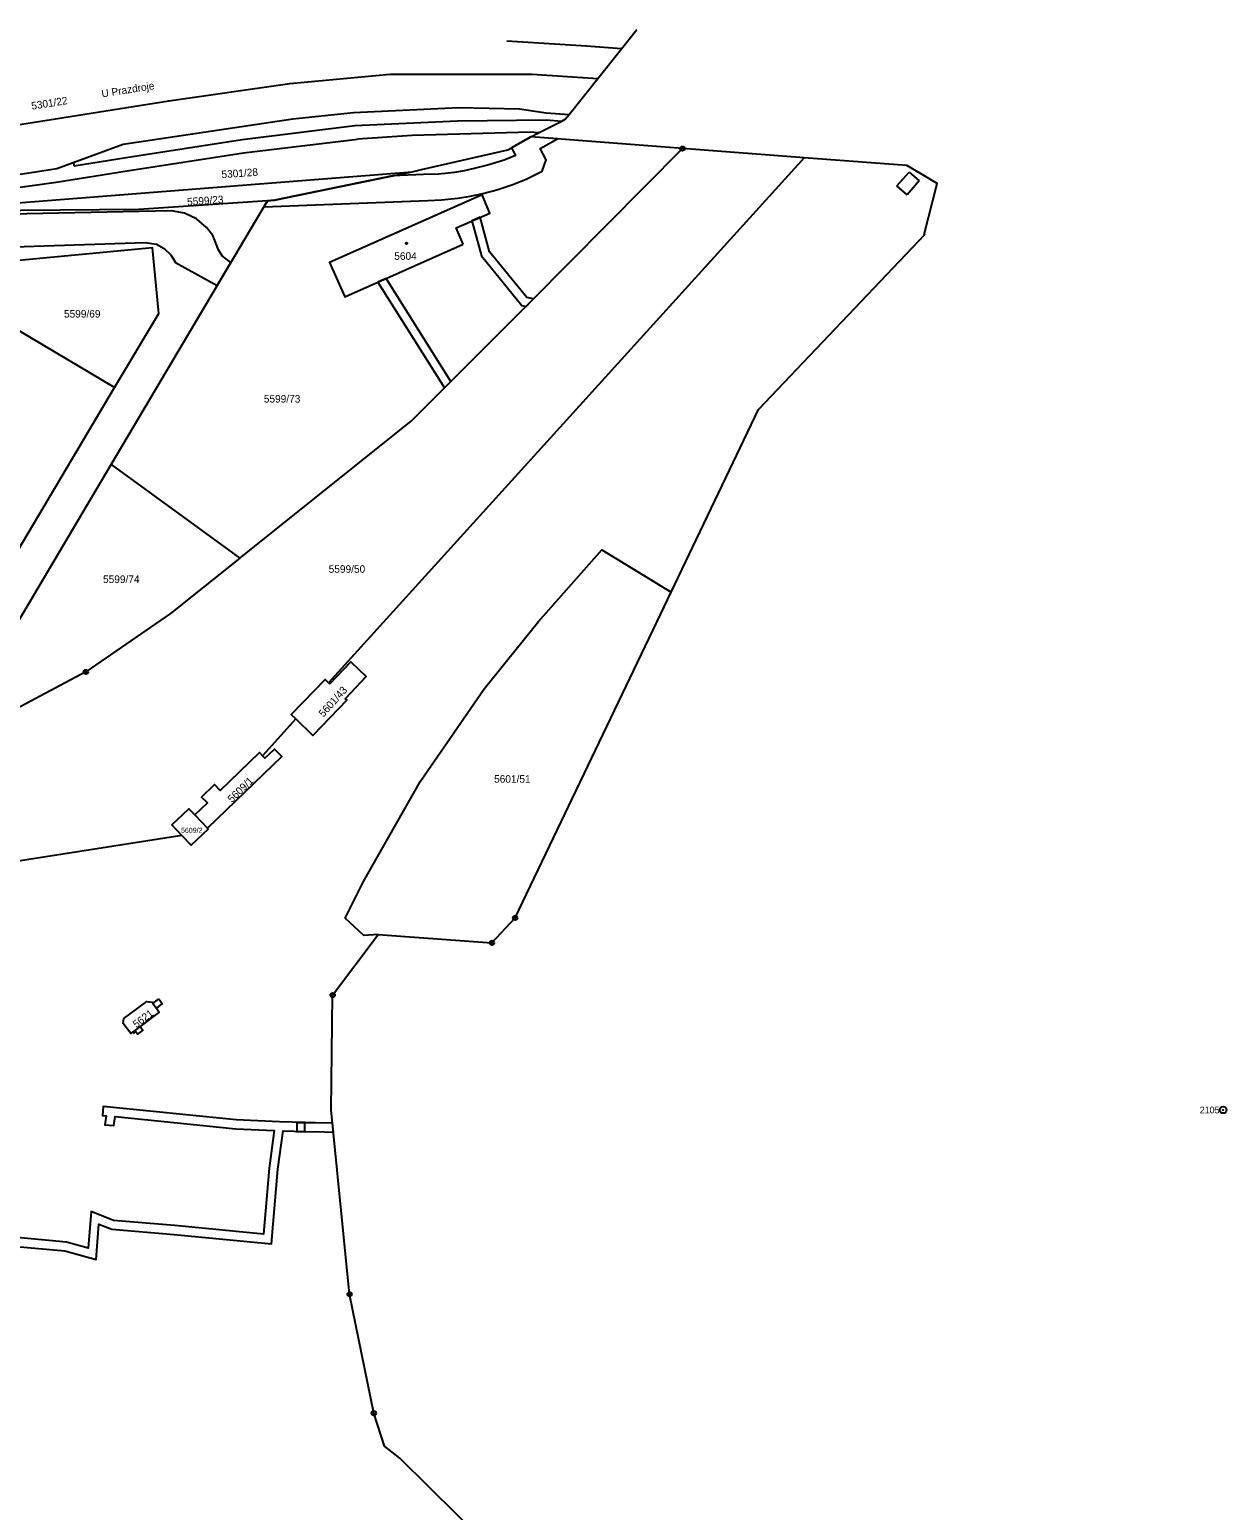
# Model space of a CAD drawing. Extents: x -821458 to -820266, y -1071458 to -1069826.
# Drawn here: x -820990.7 to -820721.4, y -1070158.9 to -1069825.7 of the extents above; entities that cross this region are included whole.
import ezdxf

# ---------------------------------------------------------------- set-up
doc = ezdxf.new("R2010")
doc.units = 0
for name, color, linetype in [('Vrstva 1', 7, 'Continuous'), ('Vrstva 13', 7, 'Continuous'), ('Vrstva 2', 7, 'Continuous'), ('Vrstva 4', 7, 'Continuous'), ('Vrstva 5', 7, 'Continuous'), ('Vrstva 7', 7, 'Continuous'), ('Vrstva 8', 7, 'Continuous')]:
    doc.layers.add(name, color=color, linetype=linetype)

msp = doc.modelspace()

# ---------------------------------------------------------------- linework, layer by layer
at = {"layer": 'Vrstva 1'}
for p, q in [((-820857.47, -1069830.03), (-820854.02, -1069825.73)), ((-820862.85, -1069836.75), (-820857.47, -1069830.03)), ((-820869.29, -1069844.79), (-820862.85, -1069836.75)), ((-820877.88, -1069849.87), (-820876.16, -1069848.95)), ((-820843.79, -1069852.49), (-820877.88, -1069849.87)), ((-820816.4, -1069854.6), (-820843.79, -1069852.49)), ((-820816.4, -1069854.6), (-820923.4, -1069972.68)), ((-820904.63, -1069857.69), (-820902.53, -1069857.21)), ((-820972.32, -1069923.54), (-820937.16, -1069864.21)), ((-820971.6, -1069906.22), (-821016.17, -1069879.84)), ((-821014.57, -1069978.75), (-820971.6, -1069906.22)), ((-821007, -1069982.04), (-820972.32, -1069923.54)), ((-820972.32, -1069923.54), (-820943.38, -1069944.62)), ((-820930.78, -1069980.82), (-820938.28, -1069989.09)), ((-820953.52, -1070002.4), (-820950.64, -1070005.41)), ((-820886.66, -1070031.18), (-820881.43, -1070025.58)), ((-820922.5, -1070042.94), (-820912.23, -1070029.33)), ((-820912.23, -1070029.33), (-820886.66, -1070031.18)), ((-820887.52, -1070166.75), (-820907.37, -1070147.11))]:
    msp.add_line(p, q, dxfattribs=at)
for points in [[(-820857.47, -1069830.03), (-820865.39, -1069829.46), (-820883.3, -1069828.35)], [(-821031.28, -1069841.61), (-821065.02, -1069845.45), (-821069.86, -1069846.25), (-821072.8, -1069847.42), (-821074.6, -1069849.74), (-821075.16, -1069852.74), (-821074.35, -1069855.22), (-821072.23, -1069857.2), (-821068.35, -1069858.38), (-821063.36, -1069857.88), (-821060.54, -1069857.49), (-821058.58, -1069857.22), (-821054.1, -1069856.61), (-821050.74, -1069856.15), (-821032.05, -1069853.34), (-821030.77, -1069853.1), (-820959.33, -1069841.72), (-820932.12, -1069837.86), (-820909.53, -1069835.76), (-820877.6, -1069835.74), (-820862.85, -1069836.75)], [(-821061.99, -1069866.11), (-821057.61, -1069865.7), (-821023.88, -1069862.57), (-821005.41, -1069860.19), (-820984.58, -1069856.94), (-820980.88, -1069855.59), (-820969.65, -1069851.52), (-820931.42, -1069845.82), (-820917.79, -1069844.37), (-820894.09, -1069843.23), (-820880.46, -1069843.52), (-820874.49, -1069844.42), (-820869.29, -1069844.79)], [(-820876.16, -1069848.95), (-820870.96, -1069846.31), (-820870.19, -1069845.91), (-820869.29, -1069844.79)], [(-820943.38, -1069944.62), (-820904.83, -1069913.82), (-820877.65, -1069886.69), (-820843.79, -1069852.49)], [(-820902.53, -1069857.21), (-820883.1, -1069852.8), (-820877.88, -1069849.87)], [(-820789.2, -1069871.73), (-820789.39, -1069871.82), (-820786.45, -1069860.33), (-820790.21, -1069858.13), (-820793.27, -1069856.33), (-820816.4, -1069854.6)], [(-821062.64, -1069871.14), (-821062.15, -1069870.91), (-821010.61, -1069866.01), (-820904.63, -1069857.69)], [(-820937.16, -1069864.21), (-820935.6, -1069864.1), (-820904.63, -1069857.69)], [(-820893.15, -1069873.97), (-820894.73, -1069870.31), (-820887.1, -1069867.01), (-820888.89, -1069862.88), (-820923.18, -1069878.15), (-820919.76, -1069885.87), (-820893.15, -1069873.97)], [(-820937.16, -1069864.21), (-820966.1, -1069866.2), (-821010.4, -1069866.6), (-821062.78, -1069871.23)], [(-820846.34, -1069952.27), (-820826.67, -1069911.18), (-820789.2, -1069871.73)], [(-820971.6, -1069906.22), (-820961.64, -1069889.6), (-820963.06, -1069874.82), (-821016.17, -1069879.84)], [(-820912.23, -1070029.33), (-820915.47, -1070029.5), (-820919.68, -1070025.67), (-820915.59, -1070017.42), (-820902.76, -1069994.78), (-820888.44, -1069974.07), (-820876.16, -1069958.86), (-820861.96, -1069942.73), (-820853.71, -1069947.77), (-820846.34, -1069952.27)], [(-820943.38, -1069944.62), (-820959, -1069957.1), (-820978.04, -1069970.23), (-821006.55, -1069985.33), (-821007, -1069982.04)], [(-820881.43, -1070025.58), (-820848.74, -1069957.29), (-820846.34, -1069952.27)], [(-820923.4, -1069972.68), (-820923.13, -1069972.94), (-820918.41, -1069967.99), (-820914.98, -1069971.25), (-820919.66, -1069976.25), (-820919.29, -1069976.59), (-820926.93, -1069984.5), (-820930.78, -1069980.82)], [(-820923.4, -1069972.68), (-820924.21, -1069971.91), (-820931.83, -1069979.82), (-820930.78, -1069980.82)], [(-820953.52, -1070002.4), (-820950.68, -1069999.7), (-820951.97, -1069998.38), (-820949.05, -1069995.55), (-820947.77, -1069996.88), (-820938.97, -1069988.37), (-820938.28, -1069989.09)], [(-820938.28, -1069989.09), (-820937.72, -1069989.67), (-820935.6, -1069987.62), (-820933.96, -1069989.25), (-820950.64, -1070005.41)], [(-820956.42, -1070007.02), (-820958.67, -1070004.65), (-820954.86, -1070001.01), (-820953.52, -1070002.4)], [(-820950.64, -1070005.41), (-820950.48, -1070005.58), (-820954.31, -1070009.24), (-820956.42, -1070007.02)], [(-820956.42, -1070007.02), (-821087.99, -1070027.64), (-821182.41, -1070042.44)], [(-820913.23, -1070137.01), (-820918.68, -1070110.25), (-820922.83, -1070068.79), (-820922.5, -1070042.94)], [(-820961.6, -1070043.79), (-820960.88, -1070044.8), (-820962.17, -1070045.86), (-820961.5, -1070046.76), (-820965.8, -1070049.99), (-820965.18, -1070050.82), (-820966.42, -1070051.71), (-820966.84, -1070051.16), (-820967.25, -1070051.47), (-820967.44, -1070051.23), (-820967.91, -1070051.58), (-820969.67, -1070049.36), (-820969.48, -1070048.21), (-820964.32, -1070044.38), (-820963.14, -1070044.56), (-820962.96, -1070044.81), (-820961.6, -1070043.79)], [(-820907.37, -1070147.11), (-820910.8, -1070144.4), (-820913.23, -1070137.01)]]:
    msp.add_lwpolyline(points, dxfattribs=at)
at = {"layer": 'Vrstva 13'}
for points in [[(-820909.01, -1069858.6), (-820935.6, -1069864.1), (-820937.16, -1069864.21), (-820938, -1069865.63), (-820901.11, -1069864.14), (-820897.97, -1069864.02), (-820894.32, -1069863.65), (-820891.52, -1069863.19), (-820888.72, -1069862.57), (-820885.57, -1069861.78), (-820881.98, -1069860.6), (-820878.96, -1069859.36), (-820875.34, -1069857.56), (-820874.44, -1069855.04), (-820875.78, -1069852.47), (-820871.9, -1069850.33), (-820877.88, -1069849.87), (-820882.24, -1069852.32), (-820881.36, -1069854.07), (-820883.9, -1069855.06), (-820887.33, -1069856.16), (-820890.65, -1069856.97), (-820892.92, -1069857.48), (-820895.1, -1069857.86), (-820898.59, -1069858.21), (-820902.02, -1069858.29)], [(-820877.28, -1069886.32), (-820878.83, -1069885.98), (-820887.21, -1069875.71), (-820889.27, -1069867.95), (-820891.17, -1069868.77), (-820889.02, -1069876.63), (-820879.94, -1069887.79), (-820878.97, -1069888), (-820877.65, -1069886.69)], [(-820895.87, -1069904.88), (-820910.45, -1069881.71), (-820912.31, -1069882.54), (-820897.32, -1069906.33)], [(-820930.55, -1070071.69), (-820930.53, -1070073.69), (-820926.39, -1070073.66), (-820922.33, -1070073.79), (-820922.53, -1070071.79), (-820926.37, -1070071.66)]]:
    msp.add_lwpolyline(points, close=True, dxfattribs=at)
for points in [[(-821021.5, -1069875.52), (-820964.68, -1069873.6), (-820962.17, -1069874.02), (-820960.41, -1069874.98), (-820958.92, -1069876.39), (-820957.88, -1069878.13), (-820948.49, -1069883.33), (-820945.4, -1069878.11), (-820947.36, -1069876.59), (-820948.19, -1069875.29), (-820949.48, -1069872.02), (-820950.87, -1069870.22), (-820953.14, -1069868.27), (-820955.86, -1069867.01), (-820958.79, -1069866.51), (-821016.72, -1069867.68)], [(-820994.53, -1070099.41), (-820982.74, -1070100.49), (-820975.69, -1070102.41), (-820975.08, -1070094.47), (-820972.22, -1070095.6), (-820958.19, -1070096.81), (-820936.22, -1070098.9), (-820934.8, -1070082.08), (-820933.61, -1070073.51), (-820928.77, -1070073.61), (-820928.73, -1070071.61), (-820934.44, -1070071.49), (-820944.17, -1070071), (-820974.12, -1070068), (-820974.27, -1070070.06), (-820973.43, -1070070.12), (-820973.73, -1070072.1), (-820971.73, -1070072.3), (-820971.43, -1070070.28), (-820944.31, -1070073), (-820935.62, -1070073.43), (-820936.78, -1070081.86), (-820938.04, -1070096.72), (-820958.01, -1070094.81), (-820971.78, -1070093.62), (-820976.86, -1070091.61), (-820977.49, -1070099.85), (-820982.38, -1070098.51), (-820994.33, -1070097.43)]]:
    msp.add_lwpolyline(points, dxfattribs=at)
at = {"layer": 'Vrstva 4'}
for p, q in [((-820917.49, -1069847.31), (-820894.38, -1069846.22)), ((-820894.38, -1069846.22), (-820874.45, -1069846.06)), ((-820874.45, -1069846.06), (-820870.96, -1069846.31)), ((-820942.89, -1069850.45), (-820917.49, -1069847.31)), ((-820904.64, -1069849.53), (-820916.9, -1069850.41)), ((-820878.02, -1069848.81), (-820904.64, -1069849.53)), ((-820876.16, -1069848.95), (-820878.02, -1069848.81)), ((-820968.95, -1069854.46), (-820942.89, -1069850.45)), ((-820942.52, -1069853.42), (-820916.9, -1069850.41)), ((-820980.88, -1069855.59), (-820980.66, -1069856.39)), ((-820980.66, -1069856.39), (-820968.95, -1069854.46)), ((-820968.7, -1069857.51), (-820942.52, -1069853.42)), ((-820984.7, -1069860.03), (-820968.7, -1069857.51)), ((-820795.53, -1069860.89), (-820792.81, -1069857.76)), ((-820790.55, -1069859.75), (-820793.25, -1069862.87)), ((-820792.81, -1069857.76), (-820790.55, -1069859.75)), ((-821023.78, -1069865.56), (-820984.7, -1069860.03)), ((-820793.25, -1069862.87), (-820795.53, -1069860.89)), ((-820962.96, -1070044.81), (-820962.17, -1070045.86)), ((-820967.02, -1070050.91), (-820967.44, -1070051.23)), ((-820965.8, -1070049.99), (-820967.02, -1070050.91))]:
    msp.add_line(p, q, dxfattribs=at)
at = {"layer": 'Vrstva 5'}
msp.add_circle((-820905.89, -1069873.81), 0.175, dxfattribs=at)
at = {"layer": 'Vrstva 8'}
for centre, radius in [((-820843.79, -1069852.49), 0.5), ((-820843.79, -1069852.49), 0.0303), ((-820978.04, -1069970.23), 0.5), ((-820978.04, -1069970.23), 0.0303), ((-820881.43, -1070025.58), 0.5), ((-820881.43, -1070025.58), 0.0303), ((-820886.66, -1070031.18), 0.5), ((-820886.66, -1070031.18), 0.0303), ((-820922.5, -1070042.94), 0.5), ((-820922.5, -1070042.94), 0.0303), ((-820722.15, -1070068.79), 0.75), ((-820722.15, -1070068.79), 0.03), ((-820918.68, -1070110.25), 0.5), ((-820918.68, -1070110.25), 0.0303), ((-820913.23, -1070137.01), 0.5), ((-820913.23, -1070137.01), 0.0303)]:
    msp.add_circle(centre, radius, dxfattribs=at)

# ---------------------------------------------------------------- texts
at = {"layer": 'Vrstva 2'}
for s, rotation, p in [('5301/22', 9, (-820990.16, -1069843.75)), ('5301/28', 4, (-820947.45, -1069859.16)), ('5599/23', 4, (-820955.2, -1069865.32)), ('5601/43', 48, (-820924.57, -1069980.53)), ('5609/1', 44, (-820945.16, -1069999.77)), ('5621', 37, (-820966.68, -1070050.43))]:
    msp.add_text(s, height=1.7, rotation=rotation, dxfattribs=at).set_placement(p)
for s, height, p in [('5604', 1.7, (-820908.63, -1069877.52)), ('5599/69', 1.7, (-820982.95, -1069890.51)), ('5599/73', 1.7, (-820937.98, -1069909.63)), ('5599/50', 1.7, (-820923.39, -1069947.93)), ('5599/74', 1.7, (-820974.16, -1069950.22)), ('5601/51', 1.7, (-820886.17, -1069995.16)), ('5609/2', 1.139, (-820956.61, -1070006.43))]:
    msp.add_text(s, height=height, dxfattribs=at).set_placement(p)
at = {"layer": 'Vrstva 7'}
msp.add_text('U Prazdroje', height=1.7, rotation=9, dxfattribs=at).set_placement((-820974.37, -1069841))
at = {"layer": 'Vrstva 8'}
msp.add_text('2105', height=1.5, dxfattribs=at).set_placement((-820727.4, -1070069.54))

doc.saveas('drawing.dxf')
